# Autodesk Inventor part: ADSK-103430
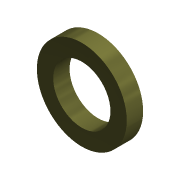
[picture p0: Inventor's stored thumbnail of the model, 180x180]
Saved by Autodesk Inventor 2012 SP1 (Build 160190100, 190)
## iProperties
Shininess: 0.0
Created: 2000-09
Part Number: ADSK-103430
Document SubType Name: Modeling
Stock Number: ADSK-103430
Density: 1 g/cm^3
Material: Default
Density: 0.0
Volumn: 0.0
Area: 0.0
PropertySet Name: Model Information
Control State: 0
Master: False
Checked Out: False
Author: gao
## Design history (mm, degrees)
node "Extrusion1" dims "d2" = 20, "d3" = 0
  sketch "Sketch1"
    geometry: C1 r 35 at (0, 0); C2 r 55 at (0, 0)
    constraints: 2 centre point, 1 coincident
    dimensions: "d0" = 70 diameter of C1; "d1" = 110 diameter of C2
body "Solid1"
